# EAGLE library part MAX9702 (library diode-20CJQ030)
Maxim's MAX9702 1.8W, Filterless, Stereo, Class D Audio Power Amplifier and DirectDrive Stereo Headphone Amplifier Description: The MAX9702 combines a highly efficient Class D speaker amplifier with a high-linearity Class AB headphone amplifier. This ensures maximum battery life in speaker mode and maximum performance in headphone mode. The MAX9702 delivers up to 1.1W per channel into an 8Ohm load and 1.8W into a 4Ohm load from a 5V power supply. Maxim's 2nd-generation, spreadspectrum modulation scheme renders the traditional Class D output filter unnecessary. The MAX9702 speaker amplifier offers two modulation schemes: a fixed-frequency (FFM) mode and a spreadspectrum (SSM) mode that reduces EMI-radiated emissions. The MAX9702 speaker amplifier features a fully differential architecture, full-bridged (BTL) output, and comprehensive click-and-pop suppression. The MAX9702 speaker amplifier features high 75dB PSRR, low 0.07% THD+N, and SNR in excess of 97dB. Shortcircuit and thermal-overload protection prevent the device from being damaged during a fault condition. The headphone amplifier uses Maxim?s patented DirectDriveTM architecture that produces a ground-referenced output from a single supply, eliminating the need for large DC-blocking capacitors, saving cost, board space, and component height. A high 80dB PSRR and low 0.02% THD+N ensures clean, low-distortion amplification of the audio signal. An I2C interface sets the speaker and headphone gain, mono, stereo, and mute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
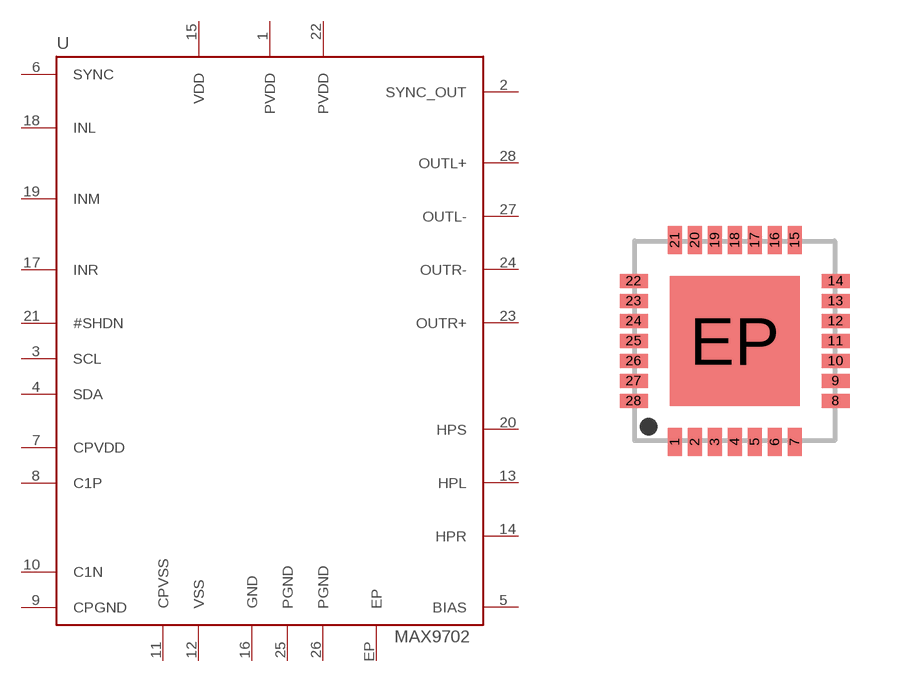
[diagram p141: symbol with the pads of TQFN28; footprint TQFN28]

Designator prefix U

## MAX9702  [TQFN28]
1  PVDD  pwr
2  SYNC_OUT  out
3  SCL  in
4  SDA
5  BIAS  in
6  SYNC  in
7  CPVDD  pwr
8  C1P  in
9  CPGND  pwr
10  C1N  in
11  CPVSS  pwr
12  VSS  pwr
13  HPL  out
14  HPR  out
15  VDD  pwr
16  GND  pwr
17  INR  in
18  INL  in
19  INM  in
20  HPS  in
21  #SHDN  in
22  PVDD  pwr
23  OUTR+  out
24  OUTR-  out
25  PGND  pwr
26  PGND  pwr
27  OUTL-  out
28  OUTL+  out
EP  EP  pas

## Footprint TQFN28 (pad centres in mm)
Maxim's TQFN28 e.g. MAX9702
smd 0.35 x 0.7: 1 -1.5,-2.525; 2 -1,-2.525; 3 -0.5,-2.525; 4 0,-2.525; 5 0.5,-2.525; 6 1,-2.525; 7 1.5,-2.525; 15 1.5,2.525; 16 1,2.525; 17 0.5,2.525; 18 0,2.525; 19 -0.5,2.525; 20 -1,2.525; 21 -1.5,2.525
smd 0.7 x 0.35: 8 2.525,-1.5; 9 2.525,-1; 10 2.525,-0.5; 11 2.525,0; 12 2.525,0.5; 13 2.525,1; 14 2.525,1.5; 22 -2.525,1.5; 23 -2.525,1; 24 -2.525,0.5; 25 -2.525,0; 26 -2.525,-0.5; 27 -2.525,-1; 28 -2.525,-1.5
smd 3.25 x 3.25: EP 0,0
